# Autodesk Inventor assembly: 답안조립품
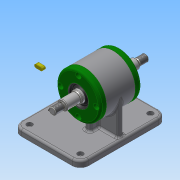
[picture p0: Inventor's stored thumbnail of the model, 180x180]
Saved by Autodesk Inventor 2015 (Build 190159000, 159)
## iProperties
Created: 2019-09
Part Number: 답안조립품
Document SubType Name: Assembly
Designer: user
Author: user
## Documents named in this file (7)
- C:\Users\user\Desktop\490904V1030\답안조립품.iam
- C:\Users\user\Desktop\490904V1030\본체.ipt
- C:\Users\user\Desktop\490904V1030\베어링 6004.ipt
- C:\Users\user\Desktop\490904V1030\축.ipt
- C:\Users\user\Desktop\490904V1030\커버.ipt
- C:\Users\user\Desktop\490904V1030\오일 실 17 30 5.ipt
- C:\Users\user\Desktop\490904V1030\키 5 x 5 x 12.ipt
